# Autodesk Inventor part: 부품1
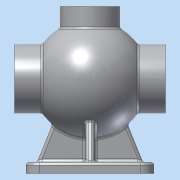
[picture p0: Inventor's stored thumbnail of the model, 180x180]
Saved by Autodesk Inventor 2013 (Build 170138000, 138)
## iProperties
Created: 2018-06
Part Number: 부품1
Material: 알루미늄 6061
Document SubType Name: Modeling
Designer: Administrator
Density: 2.71 g/cm^3
Mass: 1509.58 g
Surface Area: 1153.7 cm^2
Volume: 557.041 cm^3
Author: Administrator
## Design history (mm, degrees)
sketch "스케치1"
  geometry: L1 (68, 0)-(-68, 0); L2 (-68, 0)-(-68, 31); L3 (-68, 31)-(-42.988, 31); L4 (68, 0)-(68, 31); L5 (68, 31)-(42.988, 31); L6 (-68, 17.5)-(-39.278, 17.5); L7 (39.278, 17.5)-(68, 17.5); A1 r 53 centre (0, 0) between (42.988, 31) and (-42.988, 31); A2 r 43 centre (0, 0) between (39.278, 17.5) and (-39.278, 17.5); 2 further points
  constraints: 14 end point, 4 perpendicular, 4 point on circle, 3 coincident, 2 centre point, 2 point on line, 1 horizontal, 1 midpoint, 1 parallel
  dimensions: "d0" = 106 diameter of A1; "d1" = 86 diameter of A2; "d2" = 136 distance of L1.start L1.end; "d3" = 62 diameter of L3 L1; "d4" = 62 diameter of L5 L1; "d6" = 35 diameter of L6 L1; "d7" = 35 diameter of L7 L1
revolve "회전1" sketch "스케치1" stored, may be unused: angle "d11" = 90 deg
node "작업 평면2"
sketch "스케치2"
  geometry: C1 r 27 at (0, 0); 1 further point
  constraints: 1 centre point, 1 coincident
  dimensions: "d13" = 54 diameter of C1
extrude "돌출1" join sketch "스케치2" stored distance "d14" = 10; taper "d15" = 0 deg
sketch "스케치3"
  geometry: C1 r 27 at (0, 0) reference; C2 r 13 at (0, 0)
  constraints: 1 centre point, 1 coincident
  dimensions: "d16" = 26 diameter of C2
extrude "돌출2" cut sketch "스케치3" stored distance "d17" = 10; taper "d18" = 0 deg
node "작업 평면3"
sketch "스케치4"
  geometry: L1 (-57.5, -62.5)-(57.5, -62.5); L2 (57.5, -62.5)-(57.5, 62.5); L3 (57.5, 62.5)-(-57.5, 62.5); L4 (-57.5, 62.5)-(-57.5, -62.5); L5 (-57.5, -62.5)-(57.5, 62.5); L6 (57.5, -62.5)-(-57.5, 62.5); 1 further point
  constraints: 12 end point, 2 midpoint, 2 parallel, 1 horizontal, 1 perpendicular
  dimensions: "d20" = 115 distance of L3.end L2.end; "d21" = 125 distance of L2.end L1.end
extrude "돌출3" join sketch "스케치4" distance "d22" = 10; taper "d23" = 0 deg
sketch "스케치9"
  geometry: C1 r 17.5 at (0, 0) reference; 1 further point
  constraints: 1 vertical alignment
  dimensions: "d54" = 24 distance of C1.centre point (0, 24)
hole "구멍2" sketch "스케치9" at (0, 24) diameter "d55" = 3.242; stored, may be unused: countersink angle "d59" = 90 deg, drill point angle "d61" = 118 deg; dims "d56" = 16, "d57" = 4, "d58" = 2, "d60" = 19
sketch "스케치10"
  geometry: C1 r 31 at (0, 0) reference; 1 further point
  constraints: 1 vertical alignment
  dimensions: "d65" = 22.5 distance of C1.centre point (0, 22.5)
hole "구멍3" sketch "스케치10" at (0, 22.5) diameter "d66" = 3.242; stored, may be unused: countersink angle "d70" = 90 deg, drill point angle "d72" = 118 deg; dims "d67" = 12, "d68" = 4, "d69" = 2, "d71" = 15
sketch "스케치11"
  geometry: C1 r 13 at (0, 0) reference; 1 further point
  constraints: 1 horizontal alignment
  dimensions: "d76" = 20 distance of C1.centre point (20, 0)
hole "구멍4" sketch "스케치11" at (20, 0) diameter "d77" = 3.242; stored, may be unused: countersink angle "d81" = 90 deg, drill point angle "d83" = 118 deg; dims "d78" = 9, "d79" = 4, "d80" = 2, "d82" = 11
fillet "모깎기1" dims "d87" = 12
sketch "스케치12"
  geometry: C1 r 6 at (-45.5, 50.5); C2 r 6 at (45.5, 50.5); A1 r 12 centre (45.5, 50.5) between (57.5, 50.5) and (45.5, 62.5) reference; A2 r 12 centre (-45.5, 50.5) between (-45.5, 62.5) and (-57.5, 50.5) reference; 1 further point
  constraints: 2 centre point, 2 coincident
  dimensions: "d88" = 12 diameter of C1; "d89" = 12 diameter of C2
extrude "돌출6" cut sketch "스케치12" distance "d90" = 3; taper "d91" = 0 deg
sketch "스케치13"
  geometry: L1 (45.5, 62.5)-(-45.5, 62.5) reference; L2 (-4, -52.5)-(4, -52.5); L3 (4, -52.5)-(4, 52.5); L4 (4, 52.5)-(-4, 52.5); L5 (-4, 52.5)-(-4, -52.5); L6 (-4, -52.5)-(4, 52.5); L7 (4, -52.5)-(-4, 52.5); 1 further point
  constraints: 12 end point, 2 midpoint, 2 parallel, 1 horizontal, 1 perpendicular
  dimensions: "d92" = 8 distance of L3.end L4.end; "d94" = 10 distance between parallel lines of L1 L4
extrude "돌출7" join sketch "스케치13" stored distance "d95" = 3; taper "d96" = 0 deg
feature "면 기울기1" dims angle "d97" = 22 deg
sketch "스케치14"
  geometry: L1 (47.5, -75)-(40.87, -58.59); L2 (39.5, -75)-(51.5, -75) reference; L3 (57.5, -75)-(57.5, -85) reference; 1 further point
  constraints: 2 end point, 1 point on line
  dimensions: "d98" = 10 distance from line of L1.start L3; "d99" = 22 deg angle of L1 L3
feature "리브2" sketch "스케치14" dims "d100" = 1, "d101" = 8, "d102" = 0, "d103" = 0, "d104" = 1, "d105" = 1
hole "구멍5" diameter "d108" = 8; stored, may be unused: countersink angle "d112" = 90 deg, drill point angle "d114" = 0 deg; dims "d106" = 10, "d107" = 10, "d109" = 9, "d110" = 4, "d111" = 2, "d113" = 11
node "작업 평면4"
sketch "스케치15"
  geometry: L1 (-27, 0)-(27, 0) reference; 2 further points
  constraints: 1 vertical alignment, 1 other
  dimensions: "d115" = 10 distance from line of L1 point (0, -10)
feature "엠보싱1" sketch "스케치15" dims "d0" = 106, "d1" = 86, "d2" = 136, "d3" = 62, "d4" = 62, "d6" = 35, "d7" = 35, "d116" = 0.5, "d117" = 0
sketch "스케치17"
  geometry: L1 (50.25, 17.5)-(52, 17.5); L2 (52, 17.5)-(52, 18.5); L3 (52, 18.5)-(50.25, 18.5); L4 (50.25, 18.5)-(50.25, 17.5); L5 (68, -31)-(68, 31) reference; L6 (-95.2, 0)-(95.2, 0) reference; 1 further point
  constraints: 8 end point, 2 parallel, 1 horizontal, 1 perpendicular
  dimensions: "d120" = 1.75 distance of L1.start L1.end; "d122" = 18.5 distance from line of L3 point (0, 0); "d123" = 16 distance between parallel lines of L5 L2; "d124" = 17.5 distance from line of L1 point (0, 0)
revolve "회전2" sketch "스케치17" stored, may be unused: angle "d125" = 90 deg
fillet "모깎기2" dims "d126" = 3
fillet "모깎기3" dims "d127" = 3
fillet "모깎기4" dims "d128" = 3
chamfer "모따기1" distance "d129" = 1; stored, may be unused: second distance "d130" = 2, angle "d131" = 45 deg
node "솔리드1"
pattern_circular "원형 패턴2" dims angle "d63" = 360 deg
pattern_circular "원형 패턴3" dims angle "d74" = 360 deg
pattern_circular "원형 패턴4" dims angle "d85" = 360 deg
mirror "대칭2"
mirror "대칭3"
mirror "대칭4"
other parameters: "d12" = 65, "d19" = -85
